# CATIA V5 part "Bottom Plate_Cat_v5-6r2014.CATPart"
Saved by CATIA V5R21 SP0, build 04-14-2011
Part number: Bottom Plate
Bounding box of the stored display mesh (mm): x -125 to 125, y 0 to 150, z 0 to 30
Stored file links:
  D:\CATIA V5R21 E-RESOURCES\CATIA-V5R21\catia-v5r21-Tut\c12-catia-v5r21-tut\c12-catia-v5r21-tut02\Bottom Plate_Cat_v5r21.CATPart
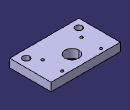
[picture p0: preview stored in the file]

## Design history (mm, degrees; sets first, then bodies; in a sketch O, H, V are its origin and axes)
Body1 (main body)
  Sketch1 on xy-plane, origin (0, 0, 0), H (1, 0, 0), V (0, 1, 0)
    point P1 (-125, 0)
    line L1 (-125, 0) -> (125, 0)
    line L2 (125, 0) -> (125, 150)
    line L3 (125, 150) -> (-125, 150)
    line L4 (-125, 150) -> (-125, 0)
    circle A1 centre (0, 100) radius 25
    point P5 (0, 100)
    circle A2 centre (95, 30) radius 12.5
    point P6 (95, 30)
    circle A3 centre (-95, 30) radius 12.5
    circle A4 centre (-70, 135) radius 5
    point P8 (-70, 135)
    construction line L5 (-25, 100) -> (25, 100)
    point P9 (-25, 100)
    point P10 (25, 100)
    construction line L6 (0, 125) -> (0, 75)
    point P11 (0, 125)
    point P12 (0, 75)
    circle A5 centre (-70, 65) radius 5
    circle A6 centre (70, 135) radius 5
    circle A7 centre (70, 65) radius 5
    length L1 = 250
    length L2 = 150
    radius A1 = 25
    distance P5 L1 = 100
    distance P6 L2 = 30
    distance L1 P6 = 30
    radius A2 = 12.5
    distance P5 P8 V = 35
    distance P5 P8 H = 70
    radius A4 = 5
    distance L1 L5 = 100
    coincidence: P1 H, P5 V, P9 A1, P10 A1, P11 A1, P11 V, P12 A1
    horizontal: L1 H, L3 H, L5 H
    vertical: L2 V, L4 V, L6 V
    symmetry: L4 L2 V, A2 A3 V, A4 A5 L5, A4 A6 L6, A5 A7 L6
  Pad1: profile Sketch1, direction (0, 0, 1), length 30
